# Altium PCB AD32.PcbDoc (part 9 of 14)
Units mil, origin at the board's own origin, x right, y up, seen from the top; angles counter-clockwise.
Board outline 7007.87 x 4368.85 mil, 12 copper layers (Top Layer, Int1 (GND), Int2 (AVDD), Int3 (DVDD), Int4 (GND), Int5 (ST), Int6 (SB), Int8 (AGND), Int7 (AVCC), Int9 (VCCA), Int10 (GND), Bottom Layer), stack 60.136 mil thick; 1350 components, 880 nets, 4712 pads, 2835 vias.
Unrouted connection lines stored in the file: 19.
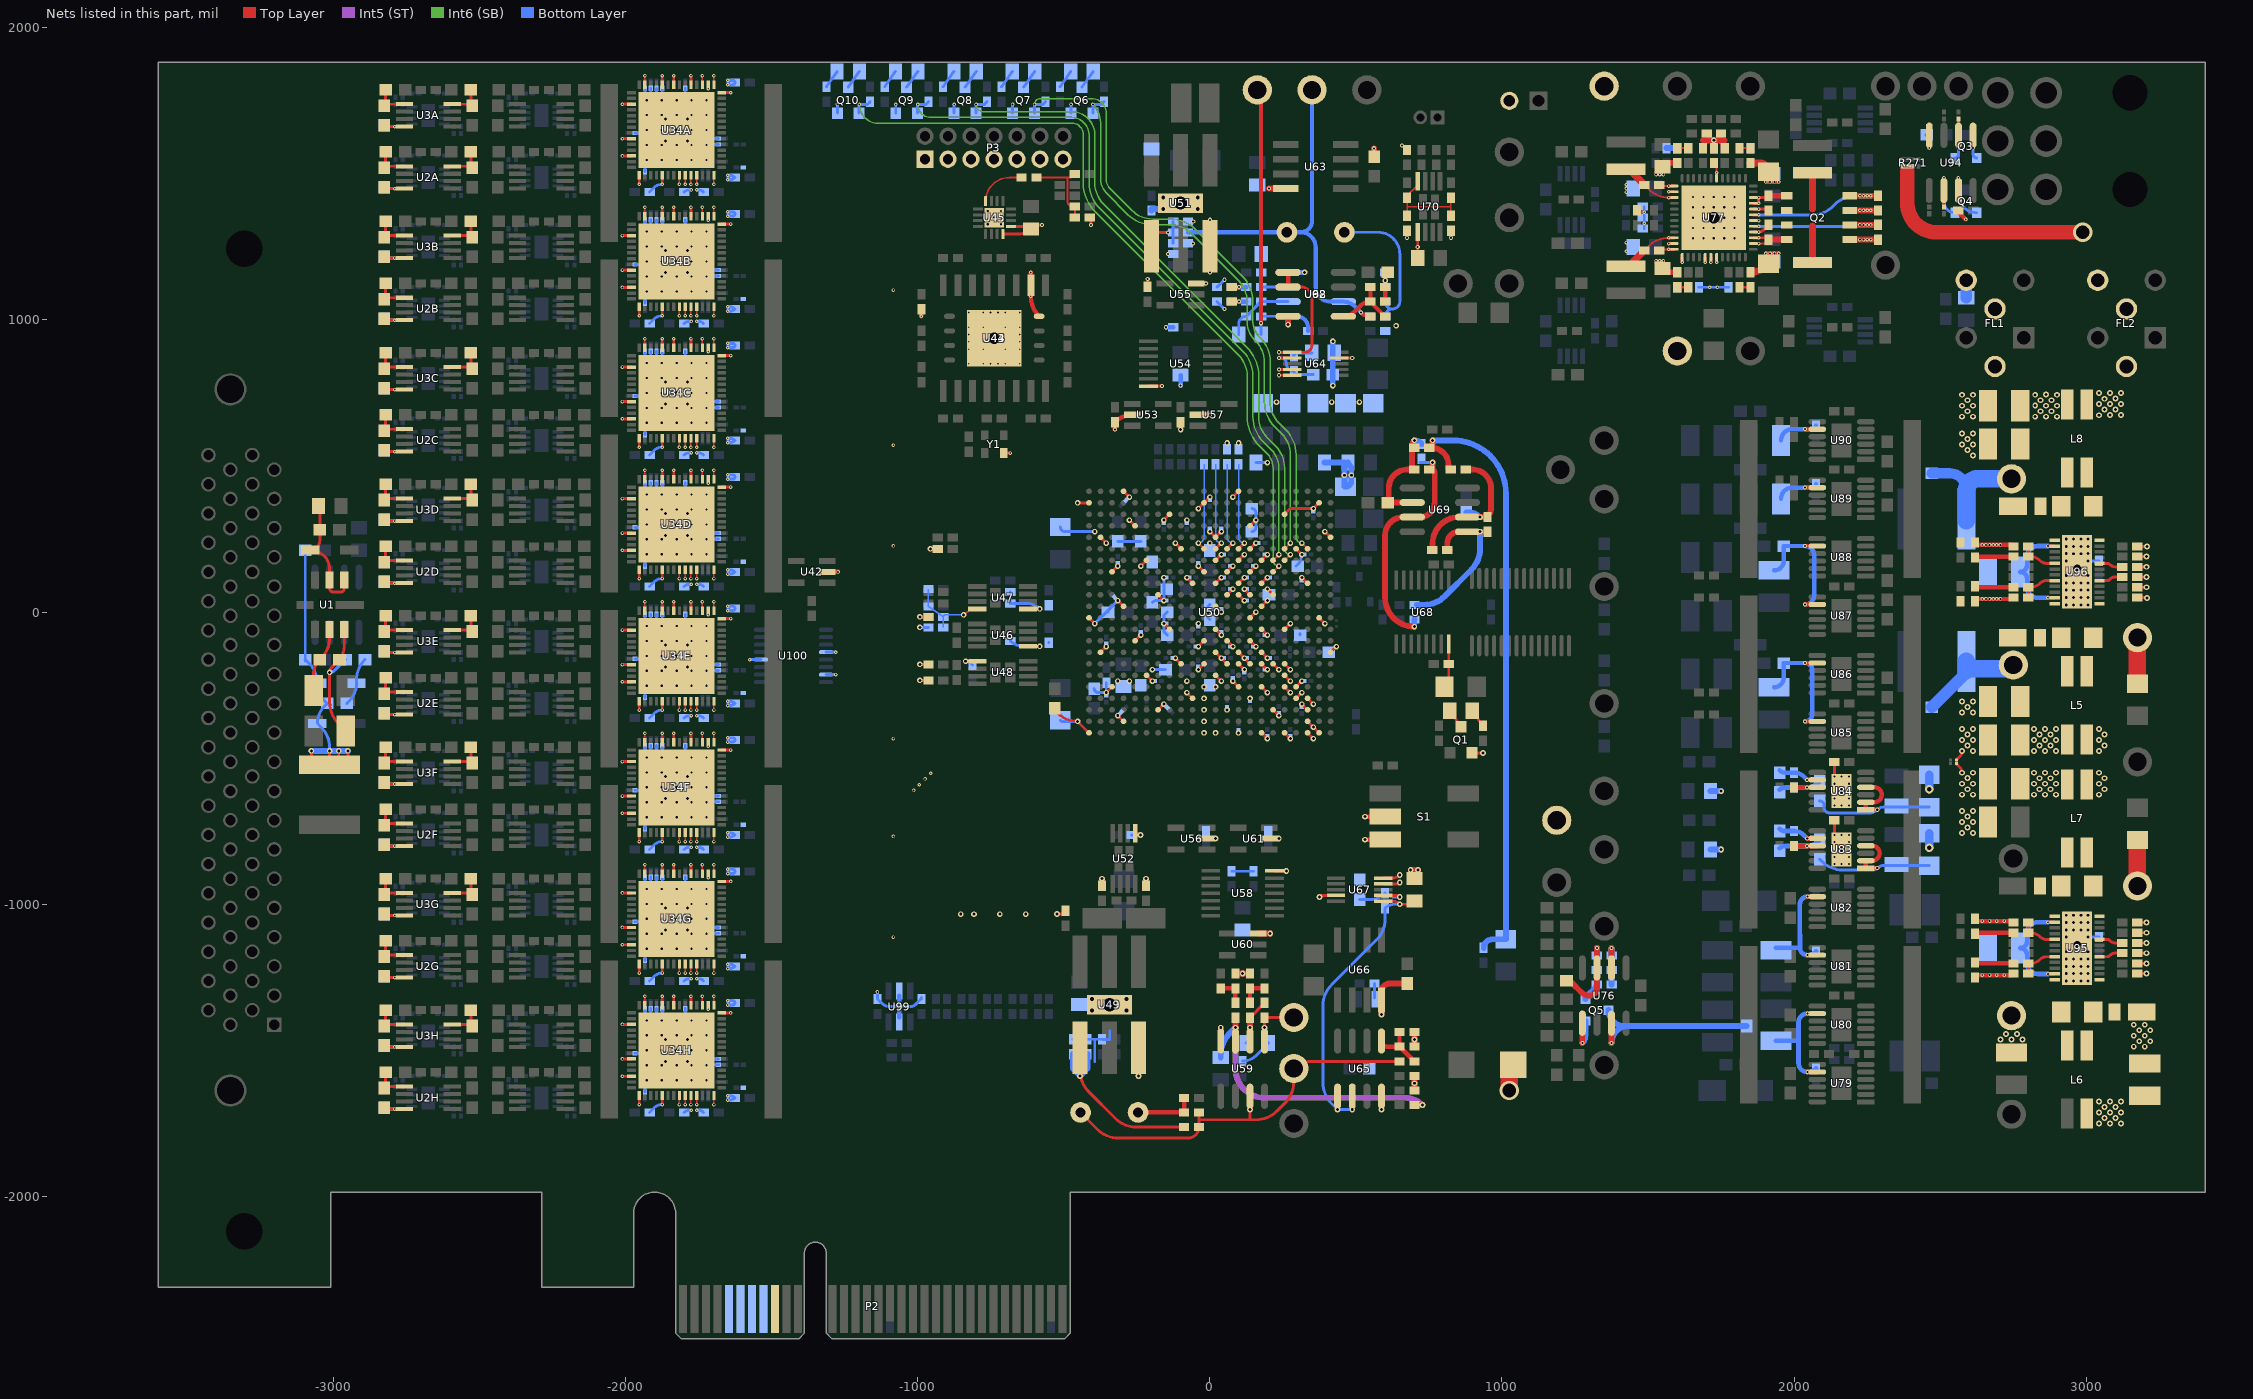
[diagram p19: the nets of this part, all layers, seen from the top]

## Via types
v1: diameter 12, hole 6, Top Layer to Bottom Layer, tented both sides, 1497 vias
v2: diameter 20, hole 10, Top Layer to Bottom Layer, tented both sides, 364 vias
v3: diameter 19, hole 10, Top Layer to Bottom Layer, tented both sides, 347 vias
v4: diameter 14, hole 7, Top Layer to Bottom Layer, tented both sides, 228 vias
v5: diameter 19.68, hole 7.87, Top Layer to Bottom Layer, 225 vias
v6: diameter 19.02, hole 10, Top Layer to Bottom Layer, tented both sides, 85 vias
v7: diameter 20, hole 10, Top Layer to Bottom Layer, 32 vias
v8: diameter 40, hole 20, Top Layer to Bottom Layer, tented both sides, 14 vias
v9: diameter 30, hole 15, Top Layer to Bottom Layer, tented both sides, 12 vias
v10: diameter 25, hole 13, Top Layer to Bottom Layer, 8 vias
v11: diameter 40, hole 20, Top Layer to Bottom Layer, 6 vias
v12: diameter 50, hole 20, Top Layer to Bottom Layer, 6 vias
v13: diameter 66, hole 47, Top Layer to Bottom Layer, tented both sides, 3 vias
v14: diameter 63, hole 45, Top Layer to Bottom Layer, 2 vias
v15: diameter 50, hole 25, Top Layer to Bottom Layer, 2 vias
v16: diameter 12, hole 6, Top Layer to Bottom Layer, 2 vias
v17: diameter 60, hole 40, Top Layer to Bottom Layer, tented both sides, 1 vias
v18: diameter 60, hole 40, Top Layer to Bottom Layer, 1 vias

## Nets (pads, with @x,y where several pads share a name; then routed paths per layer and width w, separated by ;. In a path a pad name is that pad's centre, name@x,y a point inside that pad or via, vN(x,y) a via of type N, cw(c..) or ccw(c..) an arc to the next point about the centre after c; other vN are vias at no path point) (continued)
GND: (continued)
  other v2: 700.59,-1612.5 3162.5,-1487.5 3200,-1487.5 3181.25,-1468.75 3218.75,-1468.75 700.59,-1462.5 2706.25,-1462.5 2743.75,-1462.5 2781.25,-1462.5 3162.5,-1450 3200,-1450 2725,-1443.75 2762.5,-1443.75 3181.25,-1431.25 3218.75,-1431.25 3162.5,-1412.5 3200,-1412.5 2931.25,-1262.5 2956.25,-1262.5 2981.25,-1262.5 3006.25,-1262.5 2931.25,-1237.5 2956.49,-1237.69 2981.49,-1237.69 3006.25,-1237.5 112.5,-1236.91 2931.25,-1212.5 2956.49,-1212.69 2981.25,-1212.5 3006.25,-1212.5 2931.25,-1187.5 2956.25,-1187.5 2981.25,-1187.5 3006.25,-1187.5 2931.25,-1162.5 3006.25,-1162.5 2931.25,-1112.5 2931.25,-1087.5 2956.49,-1087.69 2981.49,-1087.69 3006.25,-1087.5 2931.25,-1062.5 2956.49,-1062.69 2981.49,-1062.69 3006.25,-1062.5 2931.25,-1037.5 2956.25,-1037.5 2981.25,-1037.5 3006.25,-1037.5 2575,-756.25 2612.5,-756.25 2593.75,-737.5 2575,-718.75 2612.5,-718.75 2593.75,-700 2575,-681.25 2612.5,-681.25 2575,-625 2612.5,-625 3043.75,-625 2593.75,-606.25 3062.5,-606.25 2575,-587.5 2612.5,-587.5 3043.75,-587.5 3062.5,-568.75 2593.75,-567.5 2575,-550 2612.5,-550 3043.75,-550 2612.5,-475 3043.75,-475 2593.75,-456.25 3062.5,-456.25 2575,-437.5 2612.5,-437.5 3043.75,-437.5 2593.75,-418.75 3062.5,-418.75 2575,-400 2612.5,-400 3043.75,-400 2575,-343.75 2612.5,-343.75 2593.75,-325 2575,-306.25 2612.5,-306.25 2931.25,25 2956.25,25 2981.25,25 3006.25,25 2956.49,49.81 2981.49,49.81 2931.25,50 3006.25,50 2956.49,74.81 2931.25,75 2981.25,75 3006.25,75 2931.25,100 2956.25,100 2981.25,100 3006.25,100 2931.25,125 3006.25,125 2931.25,175 2956.49,199.81 2981.49,199.81 2931.25,200 3006.25,200 2956.49,224.81 2981.49,224.81 2931.25,225 3006.25,225 2931.25,250 2956.25,250 2981.25,250 3006.25,250 2612.5,536.25 2593.75,555 2575,573.75 2612.5,573.75 2593.75,592.5 2575,611.25 2612.5,611.25 2575,668.75 2612.5,668.75 3043.75,673.75 3081.25,675 3118.75,675 2593.75,687.5 3062.5,693.75 3100,693.75 2575,706.25 2612.5,706.25 3043.75,712.5 3081.25,712.5 3118.75,712.5 2593.75,725 3062.5,730 3100,731.25 2575,743.75 2612.5,743.75 3043.75,750 3081.25,750 3118.75,750
  other v3: -19.68,-413.39 19.69,-413.39 98.43,-413.39 -19.68,-374.02 -19.68,-334.65 59.06,-334.65 -19.68,-295.28 137.8,-295.28 -19.68,-255.91 19.69,-255.91 -314.96,-236.22 -275.59,-236.22 -78.74,-236.22 -39.37,-39.37 -6.25,-1.25 0,236.22 -78.74,314.96 59.06,578.74 98.43,578.74 228.35,718.5 417.32,718.5 511.81,718.5
  other v4: 2137.5,-862.5 2162.5,-862.5 2187.5,-862.5 2137.5,-837.5 2187.5,-837.5 2137.5,-787.5 2187.5,-787.5 2162.5,-762.5 2187.5,-762.5 2137.5,-662.5 2162.5,-662.5 2187.5,-662.5 2137.5,-637.5 2187.5,-637.5 2137.5,-587.5 2187.5,-587.5 2162.5,-562.5 2187.5,-562.5 0,1162.74 -143.31,1225 711.61,1250 -57.72,1261.53 -56.69,1337.5 0,1342.74
  other v5: -1876.18,-1551.18 -1825,-1551.18 -1773.82,-1551.18 -1876.18,-1500 -1825,-1500 -1773.82,-1500 -1876.18,-1448.82 -1825,-1448.82 -1773.82,-1448.82 -1876.18,-1101.18 -1825,-1101.18 -1773.82,-1101.18 -1876.18,-1050 -1825,-1050 -1773.82,-1050 -1876.18,-998.82 -1825,-998.82 -1773.82,-998.82 -1876.18,-651.18 -1825,-651.18 -1773.82,-651.18 -1876.18,-600 -1825,-600 -1773.82,-600 -1876.18,-548.82 -1825,-548.82 -1773.82,-548.82 -1876.18,-201.18 -1825,-201.18 -1773.82,-201.18 -1876.18,-150 -1825,-150 -1773.82,-150 -1876.18,-98.82 -1825,-98.82 -1773.82,-98.82 -1876.18,248.82 -1825,248.82 -1773.82,248.82 -1876.18,300 -1825,300 -1773.82,300 -1876.18,351.18 -1825,351.18 -1773.82,351.18 -1876.18,698.82 -1825,698.82 -1773.82,698.82 -1876.18,750 -1825,750 -1773.82,750 -1876.18,801.18 -1825,801.18 -1773.82,801.18 -1876.18,1148.82 -1825,1148.82 -1773.82,1148.82 -1876.18,1200 -1825,1200 -1773.82,1200 -1876.18,1251.18 -1825,1251.18 -1773.82,1251.18 1654.13,1279.13 1689.57,1279.13 1725,1279.13 1760.43,1279.13 1795.87,1279.13 1654.13,1314.57 1689.57,1314.57 1725,1314.57 1760.43,1314.57 1795.87,1314.57 1654.13,1350 1689.57,1350 1725,1350 1760.43,1350 1795.87,1350 1654.13,1385.43 1689.57,1385.43 1725,1385.43 1760.43,1385.43 1795.87,1385.43 1654.13,1420.87 1689.57,1420.87 1725,1420.87 1760.43,1420.87 1795.87,1420.87 -1876.18,1598.82 -1825,1598.82 -1773.82,1598.82 -1876.18,1650 -1825,1650 -1773.82,1650 -1876.18,1701.18 -1825,1701.18 -1773.82,1701.18
  other v6: -852.36,-1033.46 -807.09,-1033.46 -718.5,-1033.46 -629.92,-1033.46 637.5,980 600.59,1134.56
  other v10: -402.81,-1363.43 -284.69,-1363.43 -402.81,-1324.06 -284.69,-1324.06 -40.94,1380.06 -159.06,1419.43 -40.94,1419.43
  other v11: 2162.5,-812.5 2162.5,-612.5
  other v14: -343.75,-1343.75 -100,1399.74
  other v15: 2968.75,-1137.5 2968.75,150
  other v17: -737.5,937.5
  other v18: 1725,1350
INIT: R369.1 U50.U12 | length 308.8
  Top Layer w5: v3(-39.37,236.22) U50.U12@-19.68,216.54
  Bottom Layer w5: v3(-39.37,236.22) ccw(c-39.37,255.91) -19.68,255.91 R369.1@-19.69,505.91
JTAG1: P2.B9
JTAG2: P2.A5
JTAG3: P2.A6
JTAG4: P2.A7
JTAG5: P2.A8
LED_A: Q10.1 R399.1 U50.R6 | length 2662.1
  Top Layer w5: U50.R6@216.54,137.8 v3(236.22,157.48)
  Int6 (SB) w5: v1(-1200,1737.5) ccw(c-1135.73,1737.5) -1135.73,1673.23 -472.44,1673.23 cw(c-472.44,1633.86) -433.07,1633.86 -433.07,1468.6 ccw(c-293.7,1468.6) -392.25,1370.05 98.66,879.13 cw(c27.95,808.42) 127.95,808.42 127.95,667.97 ccw(c267.32,667.97) 168.77,569.42 196.85,541.34 cw(c149.33,493.82) 216.54,493.82 216.54,177.17 ccw(c236.22,177.17) v3(236.22,157.48)
  Bottom Layer w10: Q10.1@-1200.1,1708.21 -1200,1725.39 v1(-1200,1737.5) -1171.91,1737.5 R399.1@-1162.5,1746.91
LED_B: Q9.1 R394.1 U50.T6 | length 2431.2
  Top Layer w5: U50.T6@216.54,177.17 v3(236.22,196.85)
  Int6 (SB) w5: v1(-1000,1737.5) ccw(c-955.41,1737.5) -955.41,1692.91 -472.44,1692.91 cw(c-472.44,1633.86) -413.39,1633.86 -413.39,1468.6 ccw(c-293.7,1468.6) -378.33,1383.97 112.58,893.05 cw(c27.95,808.42) 147.64,808.42 147.64,667.97 ccw(c267.32,667.97) 182.69,583.34 210.77,555.26 cw(c149.33,493.82) 236.22,493.82 v3(236.22,196.85)
  Bottom Layer w10: Q9.1@-1000.1,1708.21 -1000,1708.31 v1(-1000,1737.5) -971.91,1737.5 R394.1@-962.5,1746.91
LED_C: Q8.1 R389.1 U50.T5 | length 2262.2
  Top Layer w5: U50.T5@255.91,177.17 v3(275.59,196.85)
  Int6 (SB) w5: v1(-800,1737.5) ccw(c-775.1,1737.5) -775.1,1712.6 -472.44,1712.6 cw(c-472.44,1633.86) -393.7,1633.86 -393.7,1468.6 ccw(c-293.7,1468.6) -364.41,1397.88 126.5,906.97 cw(c27.95,808.42) 167.32,808.42 167.32,667.97 ccw(c267.32,667.97) 196.61,597.25 224.69,569.18 cw(c149.33,493.82) 255.91,493.82 255.91,216.54 ccw(c275.59,216.54) v3(275.59,196.85)
  Bottom Layer w10: Q8.1@-800.1,1708.21 -800,1708.31 v1(-800,1737.5) -771.91,1737.5 R389.1@-762.5,1746.91
LED_D: Q7.1 R381.1 U50.U3 | length 2190.7
  Top Layer w5: v3(314.96,236.22) U50.U3@334.65,216.54
  Int6 (SB) w5: v1(-600,1737.5) cw(c-579.63,1737.5) -579.63,1757.87 -405.51,1757.87 cw(c-405.51,1706.69) -354.33,1706.69 -354.33,1482.09 ccw(c-307.28,1482.09) -340.55,1448.82 -266.32,1374.59 ccw(c-195.61,1445.3) -195.61,1345.3 -134.75,1345.3 cw(c-134.75,1225.61) -50.12,1310.24 112.58,1147.54 cw(c27.95,1062.91) 147.64,1062.91 147.64,992.41 ccw(c214.85,992.41) 167.32,944.88 171.64,940.57 cw(c87.01,855.94) 206.69,855.94 206.69,718.87 ccw(c306.69,718.87) 235.98,648.16 260.22,623.92 cw(c175.59,539.29) 295.28,539.29 295.28,255.91 ccw(c314.96,255.91) v3(314.96,236.22)
  Bottom Layer w10: Q7.1@-600.1,1708.21 -600,1708.31 v1(-600,1737.5) -571.91,1737.5 R381.1@-562.5,1746.91
LED_PG: Q6.1 R378.1 U50.U5 | length 1930.7
  Top Layer w5: U50.U5@255.91,216.54 v3(275.59,236.22)
  Int6 (SB) w5: v1(-400,1737.5) cw(c-462.73,1674.77) -374.02,1674.77 -374.02,1482.09 ccw(c-307.28,1482.09) -354.47,1434.9 -280.24,1360.67 ccw(c-195.61,1445.3) -195.61,1325.61 -134.75,1325.61 cw(c-134.75,1225.61) -64.04,1296.32 98.66,1133.62 cw(c27.95,1062.91) 127.95,1062.91 127.95,992.41 ccw(c214.85,992.41) 153.4,930.96 157.72,926.65 cw(c87.01,855.94) 187.01,855.94 187.01,718.87 ccw(c306.69,718.87) 222.06,634.24 246.3,610 cw(c175.59,539.29) 275.59,539.29 v3(275.59,236.22)
  Bottom Layer w10: Q6.1@-400.1,1708.21 -400,1708.31 v1(-400,1737.5) -371.91,1737.5 R378.1@-362.5,1746.91
M0: R367.1 U50.U11 | length 308.8
  Top Layer w10: U50.U11@19.69,216.54 v3(39.37,236.22)
  Bottom Layer w5: R367.1@19.69,505.91 19.69,255.91 ccw(c39.37,255.91) v3(39.37,236.22)
M1: R366.1 U50.U10 | length 308.8
  Top Layer w10: U50.U10@59.06,216.54 v3(78.74,236.22)
  Bottom Layer w5: R366.1@59.06,505.91 59.06,255.91 ccw(c78.74,255.91) v3(78.74,236.22)
M2: R365.1 U50.U9 | length 308.8
  Top Layer w10: U50.U9@98.43,216.54 v3(118.11,236.22)
  Bottom Layer w5: R365.1@98.43,505.91 98.43,255.91 ccw(c118.11,255.91) v3(118.11,236.22)
MON: C52.2 R181.2 R182.1 U65.5 | length 194.8
  Top Layer w15: U65.5@587.5,-1468.01 ccw(c606.99,-1468.01) 606.99,-1487.5 R182.1@649.41,-1487.5 ; C52.2@649.41,-1437.5 R182.1@649.41,-1487.5 ; R182.1@650.42,-1487.92 ccw(c649.41,-1488.93) R182.1@649.41,-1487.5 ; R182.1@650.42,-1487.92 699.58,-1537.08 ccw(c700.59,-1536.07) R181.2@700.59,-1537.5
MON2: C48.2 R178.2 R179.1 U62.5 | length 230.7
  Top Layer w14: 517.5,1050 cw(c547.68,1019.82) 547.68,1062.5 R179.1@549.41,1062.5 ; C48.2@549.41,1112.5 R179.1@549.41,1062.5 ; R179.1@550.59,1062.01 600.1,1012.5 R178.2@600.59,1012.5 ; R179.1@550.58,1062.02 ccw(c549.41,1060.84) R179.1@549.41,1062.5
  Top Layer w15: U62.5@456.99,1012.5 ccw(c456.99,1068.06) 496.27,1028.77 517.5,1050
NetC1_2: C1.2 D1.2 D2.1 R1.1 R665.2 R666.2 | length 1188
  Top Layer w10: v3(-3075,-475) -3075,-522.64 C1.2@-3012.5,-522.64 ; v3(-3012.5,-475) C1.2@-3012.5,-522.64 ; v3(-2981.25,-475) C1.2@-2981.25,-522.64 ; v3(-2950,-475) -2950,-522.64 C1.2@-2981.25,-522.64 ; C1.2@-3012.5,-522.64 C1.2@-2981.25,-522.64
  Bottom Layer w10: R665.2@-3096.25,-162.5 R665.2@-3095.96,-162.21 ; R665.2@-3095.96,-167.04 R665.2@-3095.96,-162.5 ; R666.2@-3095.96,212.5 R665.2@-3095.96,-162.21 ; D1.2@-3060.43,-237.75 D1.2@-3054.43,-243.75 ; v3(-3012.5,-475) -3012.5,-464.6 ccw(c-3112.5,-464.6) -3041.79,-393.89 D2.1@-3054.43,-381.25 cw(c-2969.24,-381.25) -3029.48,-321.01 R1.1@-3020.96,-312.5 -3029.48,-303.99 cw(c-2969.24,-243.75) D1.2@-3054.43,-243.75 ; R665.2@-3095.96,-162.5 -3082.51,-175.95 cw(c-3150.31,-243.75) D1.2@-3054.43,-243.75 ; R665.2@-3095.96,-162.5 R665.2@-3095.96,-162.21
  Bottom Layer w20: v3(-3075,-475) v3(-3012.5,-475) v3(-2981.25,-475) v3(-2950,-475)
NetC2_2: C2.2 D3.2 R2.1 U1.1 U1.2 | length 434
  Top Layer w10: C2.2@-3050.89,362.5 cw(c-3050.89,357.58) -3045.96,357.58 R2.1@-3045.96,281.25 -3045.96,245.96 cw(c-3079.43,245.96) D3.2@-3079.43,212.5 cw(c-3079.43,145.57) -3012.5,145.57 U1.2@-3012.5,109.65 -3012.5,81.25 ccw(c-3000,81.25) -3000,68.75 -2975,68.75 ccw(c-2975,81.25) -2962.5,81.25 U1.1@-2962.5,109.65
NetC5_1: C5.1 R5.1 R6.1 R7.2 | length 293.5
  Top Layer w6: R6.1@-593.16,1487.5 -487.5,1487.5 ; C5.1@-461.84,1350 R5.1@-461.84,1387.5 -468.5,1387.5 cw(c-468.5,1406.5) -487.5,1406.5 -487.5,1487.5 ; R7.2@-461.84,1500 cw(c-474.34,1500) -474.34,1487.5 -487.5,1487.5
NetC7_1: C7.1 R3.2 R8.2 U1.7 | length 458.7
  Top Layer w10: R8.2@-2979.04,-162.5 R8.2@-2983.21,-166.68 ; U1.7@-2962.5,-59.65 -2962.5,-116.68 cw(c-3033.21,-116.68) R8.2@-2983.21,-166.68 ; C7.1@-2957.38,-406.25 -2983.21,-380.42 cw(c-2912.5,-309.71) -3012.5,-309.71 v3(-3012.5,-206.25) cw(c-2987.67,-206.25) -3005.23,-188.69 R8.2@-2983.21,-166.68
  Bottom Layer w10: v3(-3012.5,-206.25) ccw(c-3012.5,-181.42) -2994.94,-198.98 R3.2@-2958.46,-162.5
NetC8_1: C8.1 R8.1 U1.6 | length 224.5
  Top Layer w10: C8.1@-3067.62,-268.75 -3067.62,-214.78 cw(c-2993.69,-214.78) R8.1@-3045.96,-162.5 -3041.79,-158.32 ccw(c-3112.5,-87.61) -3012.5,-87.61 U1.6@-3012.5,-59.65
NetC38_1: C38.1 C43.2 R168.2 | length 207.6
  Top Layer w15: C38.1@-245.65,-1712.5 C43.2@-88.09,-1712.5 R168.2@-88.09,-1662.5
NetC38_2: C38.2 C43.1 R169.2 R181.1 TP5.1 U59.7 | length 1397.6
  Top Layer w10: C38.2@-442.5,-1712.5 -384.29,-1770.71 ccw(c-313.58,-1700) -313.58,-1800 -74.41,-1800 ccw(c-74.41,-1762.5) R169.2@-36.91,-1762.5 -36.91,-1737.5 ; C43.1@-36.91,-1712.5 -36.91,-1737.5 ; U59.7@137.5,-1656.99 v2(137.5,-1702.5) 137.5,-1737.5 ; R181.1@649.41,-1537.5 347.86,-1537.5 ccw(c347.86,-1622.86) TP5.1@287.5,-1562.5 287.5,-1608.58 cw(c187.5,-1608.58) 258.21,-1679.29 229.29,-1708.21 cw(c158.58,-1637.5) 158.58,-1737.5 137.5,-1737.5 ; -36.91,-1737.5 137.5,-1737.5
NetC44_2: C44.2 R172.2 R173.1 | length 98.8
  Top Layer w15: R172.2@37.5,-1288.09 C44.2@87.5,-1288.09 R173.1@87.5,-1336.91
NetC45_1: C45.1 R174.1 R176.2 | length 98.8
  Top Layer w15: R174.1@137.5,-1336.91 C45.1@137.5,-1288.09 R176.2@187.5,-1288.09
NetC46_1: C46.1 C147.2 R355.2 | length 512.6
  Bottom Layer w10: C46.1@460.63,1300 575.49,1300 cw(c575.49,1225) 650.49,1225 650.49,1062.99 cw(c625,1062.99) 625,1037.5 ; C147.2@600.59,1012.5 600.59,1013.09 cw(c625,1013.09) 625,1037.5 ; R355.2@600.59,1062.5 600.59,1061.91 ccw(c625,1061.91) 625,1037.5
NetC46_2: C46.2 C147.1 R178.1 R373.2 TP7.1 U98.7 | length 1379.5
  Top Layer w14: v4(517.5,1025) ccw(c547.68,1055.18) 547.68,1012.5 R178.1@549.41,1012.5
  Bottom Layer w14: R373.2@-74.41,1299.75 -74.41,1300 C46.2@263.78,1300 310.72,1300 ; TP7.1@350,1787.5 350,1339.28 cw(c310.72,1339.28) 310.72,1300 ; C147.1@549.41,1012.5 547.68,1012.5 cw(c547.68,1055.18) v4(517.5,1025) 496.27,1046.23 ccw(c456.99,1006.94) U98.7@456.99,1062.5 412.5,1062.5 cw(c412.5,1112.5) 362.5,1112.5 362.5,1248.22 ccw(c310.72,1248.22) 310.72,1300
NetC54_1: C54.1 R356.2 U65.1 U65.2 U67.1 | length 1092.5
  Top Layer w10: v2(437.5,-1702.5) U65.1@437.5,-1656.99 ; v2(487.5,-1702.5) U65.2@487.5,-1656.99 ; U67.1@593.21,-989.37 624.34,-989.37 cw(c624.34,-1025.66) v2(650,-1000) 671.96,-1000 ccw(c671.96,-960.35) C54.1@700,-988.39
  Bottom Layer w10: v2(487.5,-1702.5) v2(437.5,-1702.5) 416.79,-1681.79 cw(c487.5,-1611.08) 387.5,-1611.08 387.5,-1346.42 cw(c487.5,-1346.42) 416.79,-1275.71 570.71,-1121.79 ccw(c500,-1051.08) 600,-1051.08 R356.2@600,-1013.09 cw(c631.6,-1044.69) 631.6,-1000 v2(650,-1000)
NetC58_2: C58.2 FR2.1 U68.16 | length 150.6
  Top Layer w10: FR2.1@803.15,-255.91 ccw(c767.51,-220.26) 817.91,-220.26 C58.2@817.91,-177.17 U68.16@817.91,-109.25
NetC61_2: C61.2 R183.1 R184.1 R193.2 U70.4 | length 341.2
  Top Layer w5: R183.1@675,1356.84 675,1387.5 ; U70.4@711.25,1473.75 cw(c681.07,1473.75) 702.41,1452.41 679.84,1429.84 ccw(c691.51,1418.16) R184.1@675,1418.16 675,1387.5 ; C61.2@825,1356.84 825,1387.5 ; R193.2@825,1418.16 825,1387.5 ; 675,1387.5 825,1387.5
NetC62_1: C62.1 R189.2 R354.1 U69.1 | length 557.8
  Top Layer w20: R189.2@820.96,212.5 cw(c820.96,220.96) 812.5,220.96 812.5,234.83 cw(c852.67,234.83) 852.67,275 U69.1@881.99,275 948.57,275 cw(c948.57,272.98) C62.1@950,274.41
  Bottom Layer w20: R354.1@708.46,25 733.58,25 ccw(c733.58,125) 804.29,54.29 895.71,145.71 ccw(c825,216.42) 925,216.42 v3@925,275
  other v3: 925,275.59
NetC62_2: C62.2 R189.1 R192.2 R352.2 U69.2 | length 535.7
  Top Layer w20: R189.1@754.04,212.5 ccw(c754.04,220.96) 762.5,220.96 762.5,234.83 cw(c852.67,234.83) 852.67,325 U69.2@881.99,325 v3(925,325) 948.57,325 ccw(c948.57,327.02) C62.2@950,325.59 ccw(c919.82,355.77) 962.5,355.77 962.5,425 ccw(c900,425) 900,487.5 R192.2@883.46,487.5
  Bottom Layer w20: R352.2@877.5,341.54 885.08,341.54 cw(c885.08,285.08) v3(925,325)
NetC65_1: C65.1 L1.1 U77.10 | length 200.2
  Top Layer w7: C65.1@1486.91,1237.5 1501.88,1252.47 cw(c1571,1183.36) v1(1571,1281.1)
  Top Layer w10: v1(1571,1281.1) U77.10@1590.16,1281.1
  Top Layer w25: L1.1@1425,1184.15 ccw(c1425,1204.83) 1439.62,1190.21 C65.1@1486.91,1237.5
NetC65_2: C65.2 U77.12 | length 53.2
  Top Layer w7: C65.2@1538.09,1237.5 cw(c1548.31,1227.28) 1548.31,1241.73 v1(1571,1241.73)
  Top Layer w10: v1(1571,1241.73) U77.12@1590.16,1241.73
NetC66_1: C66.1 L2.1 U77.3 | length 200.2
  Top Layer w7: C66.1@1486.91,1462.5 1501.88,1447.53 ccw(c1571,1516.64) v1(1571,1418.9)
  Top Layer w10: v1(1571,1418.9) U77.3@1590.16,1418.9
  Top Layer w25: L2.1@1425,1515.85 cw(c1425,1495.17) 1439.62,1509.79 C66.1@1486.91,1462.5
NetC66_2: C66.2 U77.1 | length 53.2
  Top Layer w7: C66.2@1538.09,1462.5 ccw(c1548.31,1472.72) 1548.31,1458.27 v1(1571,1458.27)
  Top Layer w10: v1(1571,1458.27) U77.1@1590.16,1458.27
NetC70_2: C70.2 R216.1 | length 37.5
  Top Layer w10: C70.2@1600,1111.91 R216.1@1637.5,1111.91
NetC71_2: C71.2 R217.1 | length 37.5
  Top Layer w7: C71.2@1600,1588.09 R217.1@1637.5,1588.09
NetC73_2: C73.2 U77.42 | length 54.7
  Top Layer w7: C73.2@1725,1536.91 cw(c1701.24,1513.15) 1734.84,1513.15 v1(1734.84,1504.04)
  Top Layer w10: U77.42@1734.84,1484.84 v1(1734.84,1504.04)
NetC74_2: C74.2 R229.1 | length 37.5
  Top Layer w7: R229.1@1812.5,1111.91 C74.2@1850,1111.91
NetC75_2: C75.2 R230.1 | length 37.5
  Top Layer w7: R230.1@1812.5,1588.09 C75.2@1850,1588.09
NetC78_1: C78.1 U77.28 | length 62
  Top Layer w10: U77.28@1859.84,1300.79 v1(1878.54,1300.79) ccw(c1878.54,1322.9) 1894.17,1307.27 C78.1@1912.5,1325.59
NetC78_2: C78.2 L3.1 Q2.7 Q2.8 U77.26 U77.27 | length 303.4
  Top Layer w8: v1(1878.54,1261.42) 1899.51,1261.42 ccw(c1899.51,1274.41) C78.2@1912.5,1274.41 ; v1(1878.54,1281.1) 1905.81,1281.1 cw(c1905.81,1274.41) C78.2@1912.5,1274.41 ; C78.2@1913.93,1275 ccw(c1913.93,1272.98) C78.2@1912.5,1274.41
  Top Layer w10: U77.26@1859.84,1261.42 v1(1878.54,1261.42) ; U77.27@1859.84,1281.1 v1(1878.54,1281.1)
  Top Layer w20: C78.2@1913.93,1275 Q2.8@1975,1275
  Top Layer w25: L3.1@2062.5,1196.65 2062.5,1320.81
NetC79_1: C79.1 U77.32 | length 54
  Top Layer w10: U77.32@1859.84,1379.53 v1(1878.54,1379.53) 1900.14,1379.53 cw(c1900.14,1362.05) C79.1@1912.5,1374.41
NetC79_2: C79.2 L4.1 Q2.5 Q2.6 U77.33 U77.34 | length 278.9
  Top Layer w10: U77.33@1859.84,1399.21 v1(1878.54,1399.21) v1(1878.54,1418.9) ; U77.34@1859.84,1418.9 v1(1878.54,1418.9) ; C79.2@1912.5,1425.59 cw(c1896.34,1441.75) 1896.34,1418.9 v1(1878.54,1418.9)
  Top Layer w20: C79.2@1912.5,1425.59 ccw(c1913.93,1427.02) 1913.93,1425 Q2.5@1975,1425
  Top Layer w25: 2062.5,1379.96 L4.1@2062.5,1503.35
NetC80_2: C80.2 R312.2 U89.8 | length 190.8
  Top Layer w15: v4(2037.5,426.25) 2079.07,426.25 U89.8@2079.44,425.89
  Bottom Layer w15: C80.2@1955.12,387.5 cw(c1993.87,387.5) 1993.87,426.25 v4(2037.5,426.25) 2063.16,426.25 ccw(c2063.16,438.09) R312.2@2075,438.09
NetC81_2: C81.2 R313.2 U90.8 | length 190.8
  Top Layer w15: v4(2037.5,626.25) 2079.07,626.25 U90.8@2079.44,625.89
  Bottom Layer w15: C81.2@1955.12,587.5 cw(c1993.87,587.5) 1993.87,626.25 v4(2037.5,626.25) 2063.16,626.25 ccw(c2063.16,638.09) R313.2@2075,638.09
NetC82_1: C82.1 R277.2 | length 133.7
  Top Layer w15: C82.1@2618.75,-1199.41 ccw(c2621.84,-1199.41) 2621.84,-1202.5 R277.2@2750.66,-1202.5
NetC83_2: C83.2 R281.1 | length 133.7
  Top Layer w15: C83.2@2618.75,-1100.59 cw(c2621.84,-1100.59) 2621.84,-1097.5 R281.1@2750.66,-1097.5
NetC84_1: C84.1 R278.2 | length 133.7
  Top Layer w15: C84.1@2618.75,88.09 ccw(c2621.84,88.09) 2621.84,85 R278.2@2750.66,85
NetC85_2: C85.2 R284.1 | length 133.7
  Top Layer w15: C85.2@2618.75,186.91 cw(c2621.84,186.91) 2621.84,190 R284.1@2750.66,190
NetC87_1: C87.1 C105.2 C106.1 FR5.2 L6.4 L7.4 R287.2 R289.2 TP38.1 U95.2 U95.11 | length 583.9
  Top Layer w10: v1(2868.75,-1238.58) U95.11@2892.25,-1238.58 ; v1(2868.75,-1061.42) U95.2@2892.25,-1061.42 ; R287.2@3174.34,-1237.5 v2(3206.25,-1237.5) ; R289.2@3174.34,-1062.5 v2(3206.25,-1062.5)
  Top Layer w60: TP38.1@3175,-937.5 FR5.2@3175,-780.12
  Bottom Layer w16: v1(2868.75,-1238.58) 2833.58,-1238.58 cw(c2833.58,-1202.5) 2797.5,-1202.5 2797.5,-1173.63 ccw(c2773.87,-1173.63) C106.1@2773.87,-1150 ccw(c2773.87,-1126.37) 2797.5,-1126.37 2797.5,-1097.5 cw(c2833.58,-1097.5) 2833.58,-1061.42 v1(2868.75,-1061.42)
  other v2: 3043.75,-1750 3081.25,-1750 3118.75,-1750 3062.5,-1731.25 3100,-1731.25 3043.75,-1712.5 3081.25,-1712.5 3118.75,-1712.5 3062.5,-1693.75 3100,-1693.75 3043.75,-1675 3081.25,-1675 3118.75,-1675 2821.25,-625 2858.75,-625 2896.25,-625 2840,-606.25 2877.5,-606.25 2821.25,-587.5 2858.75,-587.5 2896.25,-587.5 2840,-568.75 2877.5,-568.75 2821.25,-550 2858.75,-550 2896.25,-550
NetC88_2: C88.2 C91.1 C107.1 FR6.2 L5.3 L8.4 R290.2 R292.2 TP40.1 U96.2 U96.11 | length 586.7
  Top Layer w10: v1(2868.75,48.92) U96.11@2892.25,48.92 ; v1(2868.75,226.08) U96.2@2892.25,226.08 ; R290.2@3174.34,50 3204.48,50 cw(c3204.48,45.73) v2(3207.5,48.75) ; R292.2@3174.34,225 v2(3207.5,225)
  Top Layer w60: FR6.2@3175,-244.88 TP40.1@3175,-87.5
  Bottom Layer w16: v1(2868.75,48.92) 2833.58,48.92 cw(c2833.58,85) 2797.5,85 2797.5,113.87 ccw(c2773.87,113.87) C107.1@2773.87,137.5 ccw(c2773.87,161.13) 2797.5,161.13 2797.5,190 cw(c2833.58,190) 2833.58,226.08 v1(2868.75,226.08)
  other v2: 2821.25,-475 2858.75,-475 2896.25,-475 2840,-456.25 2877.5,-456.25 2821.25,-437.5 2858.75,-437.5 2896.25,-437.5 2840,-418.75 2877.5,-418.75 2821.25,-400 2858.75,-400 2896.25,-400 2825,668.75 2862.5,668.75 2900,668.75 2843.75,687.5 2881.25,687.5 2862.5,706.25 2900,706.25 2825,707.5 2843.75,725 2881.25,725 2825,743.75 2900,743.75 2862.13,744.61
NetC89_2: C89.2 C108.2 D6.2 R275.1 R301.2 TP37.1 | length 352.5
  Bottom Layer w40: R301.2@2470.96,-325 2585.55,-210.42 ccw(c2575.13,-200) C108.2@2589.86,-200
  Bottom Layer w60: C108.2@2589.86,-200 C108.2@2589.86,-193.75 ; C108.2@2589.86,-168.75 C108.2@2589.86,-193.75 ; TP37.1@2737.5,-193.75 C108.2@2589.86,-193.75
NetC90_1: C90.1 C109.1 D7.2 R276.2 R302.2 TP35.1 | length 426.6
  Bottom Layer w35: R302.2@2470.96,475 2531.69,475 cw(c2531.69,416.83) C109.1@2589.86,416.83
  Bottom Layer w60: C109.1@2589.86,312.5 2589.86,416.83 cw(c2629.28,416.83) 2629.28,456.25 TP35.1@2737.5,456.25
NetC93_1: C93.1 R277.1 U95.8 | length 131.6
  Top Layer w10: C93.1@2801.84,-1237.5 R277.1@2801.84,-1202.5 2807.54,-1202.5 ccw(c2807.54,-1151.29) 2843.75,-1187.5 cw(c2863,-1206.75) 2863,-1179.53 U95.8@2892.25,-1179.53
NetC94_1: C94.1 R278.1 U96.8 | length 131.6
  Top Layer w10: C94.1@2801.84,50 R278.1@2801.84,85 2807.54,85 ccw(c2807.54,136.21) 2843.75,100 cw(c2863,80.75) 2863,107.97 U96.8@2892.25,107.97
NetC95_2: C95.2 R281.2 U95.5 | length 131.6
  Top Layer w10: C95.2@2801.84,-1062.5 R281.2@2801.84,-1097.5 2807.54,-1097.5 cw(c2807.54,-1148.71) 2843.75,-1112.5 ccw(c2863,-1093.25) 2863,-1120.47 U95.5@2892.25,-1120.47
NetC96_2: C96.2 R284.2 U96.5 | length 131.6
  Top Layer w10: C96.2@2801.84,225 R284.2@2801.84,190 2807.54,190 cw(c2807.54,138.79) 2843.75,175 ccw(c2863,194.25) 2863,167.03 U96.5@2892.25,167.03
NetC97_1: C97.1 D5.1 L7.1
NetC97_2: C97.2 L7.2 U95.1 U95.24
NetC98_1: C98.1 D8.1 L6.1
NetC98_2: C98.2 L6.2 U95.12 U95.13
NetC99_1: C99.1 D6.1 L5.2
NetC99_2: C99.2 L5.1 U96.12 U96.13
NetC100_1: C100.1 D7.1 L8.1
NetC100_2: C100.2 L8.2 U96.1 U96.24
NetC101_2: C101.2 U95.20 | length 81.1
  Top Layer w10: U95.20@3045.25,-1120.47 3070.32,-1120.47 cw(c3070.32,-1135.93) 3081.25,-1125 ccw(c3099.36,-1106.89) 3099.36,-1132.5 C101.2@3123.16,-1132.5
NetC102_2: C102.2 U96.20 | length 81.1
  Top Layer w10: U96.20@3045.25,167.03 3070.32,167.03 cw(c3070.32,151.57) 3081.25,162.5 ccw(c3099.36,180.61) 3099.36,155 C102.2@3123.16,155
NetC103_1: C103.1 U95.17 | length 81.5
  Top Layer w10: U95.17@3045.25,-1179.53 3070.32,-1179.53 ccw(c3070.32,-1164.07) 3081.25,-1175 3083.47,-1172.78 cw(c3096.21,-1185.51) 3096.21,-1167.5 C103.1@3123.16,-1167.5
NetC104_1: C104.1 U96.17 | length 81.5
  Top Layer w10: U96.17@3045.25,107.97 3070.32,107.97 ccw(c3070.32,123.43) 3081.25,112.5 3083.47,114.72 cw(c3096.21,101.99) 3096.21,120 C104.1@3123.16,120
NetC114_2: C114.2 C119.2 L9.2 U83.1 U83.2 U83.4 | length 577.3
  Top Layer w15: U83.4@2245.56,-799.7 2267.2,-799.7 cw(c2267.2,-825) 2292.5,-825 cw(c2266.61,-825) 2266.61,-850.89 U83.2@2245.56,-850.89 U83.1@2245.56,-876.48 v4(2284.43,-876.48)
  Bottom Layer w10: C119.2@2087.5,-845.96 2094.75,-853.21 ccw(c2165.46,-782.5) 2165.46,-882.5 2269.88,-882.5 ccw(c2269.88,-861.93) v4(2284.43,-876.48) cw(c2305.81,-897.86) 2305.81,-867.62 C114.2@2462.5,-867.62
NetC115_2: C115.2 C118.2 L10.2 U84.1 U84.2 U84.4 | length 609.8
  Top Layer w15: U84.4@2245.56,-599.7 2274.7,-599.7 cw(c2274.7,-625) 2300,-625 cw(c2274.11,-625) 2274.11,-650.89 U84.2@2245.56,-650.89 U84.1@2245.56,-676.48 v4(2284.43,-676.48)
  Bottom Layer w10: C118.2@2087.5,-645.96 cw(c2087.5,-660.07) 2101.61,-660.07 2101.61,-667.62 ccw(c2121.49,-667.62) 2121.49,-687.5 2257.81,-687.5 ccw(c2257.81,-649.86) v4(2284.43,-676.48) cw(c2305.81,-697.86) 2305.81,-667.62 C115.2@2462.5,-667.62
NetC120_1: C120.1 R309.1 U79.8 U80.8 | length 413.5
  Top Layer w16: v4(2045.19,-1574.11) U79.8@2079.44,-1574.11 ; v4(2045.19,-1374.11) U80.8@2079.44,-1374.11
  Bottom Layer w16: C120.1@1937.5,-1467.62 2015,-1467.62 ; v4(2045.19,-1374.11) ccw(c2045.19,-1404.31) 2015,-1404.31 2015,-1467.62 ; R309.1@2075,-1561.91 cw(c2045.54,-1532.44) 2045.54,-1574.11 v4(2045.19,-1574.11) cw(c2045.19,-1543.92) 2015,-1543.92 2015,-1467.62
NetC121_2: C121.2 R310.2 U81.8 U82.8 | length 420.5
  Top Layer w16: v4(2045.19,-1174.11) U81.8@2079.44,-1174.11 ; v4(2045.19,-974.11) U82.8@2079.44,-974.11
  Bottom Layer w16: C121.2@1937.5,-1148.92 2020,-1148.92 ; 2019.6,-1112.5 2019.6,-999.7 cw(c2045.19,-999.7) v4(2045.19,-974.11) ; 2020,-1105 2020,-1148.92 ; R310.2@2075,-1161.91 cw(c2045.54,-1132.44) 2045.54,-1174.11 v4(2045.19,-1174.11) cw(c2045.19,-1148.92) 2020,-1148.92
NetC122_2: C122.2 R231.1 U85.8 U86.8 | length 487.2
  Top Layer w15: v4(2037.5,-374.11) U85.8@2079.44,-374.11 ; v4(2037.5,-174.11) U86.8@2079.44,-174.11
  Bottom Layer w15: C122.2@1931.25,-257.38 ccw(c1931.25,-223.92) 1964.71,-223.92 R231.1@1964.71,-175 cw(c1965.6,-175) 1965.6,-174.11 v4(2037.5,-174.11) cw(c2037.5,-199.11) 2062.5,-199.11 2062.5,-349.11 cw(c2037.5,-349.11) v4(2037.5,-374.11)
NetC123_2: C123.2 R232.2 U87.8 U88.8 | length 494.4
  Top Layer w15: v4(2037.5,26.25) 2079.07,26.25 U87.8@2079.44,25.89 ; v4(2037.5,226.25) 2079.07,226.25 U88.8@2079.44,225.89
  Bottom Layer w15: C123.2@1931.25,142.62 ccw(c1931.25,176.08) 1964.71,176.08 R232.2@1964.71,225 cw(c1965.96,225) 1965.96,226.25 v4(2037.5,226.25) cw(c2037.5,195.37) 2068.38,195.37 2068.38,57.13 cw(c2037.5,57.13) v4(2037.5,26.25)
NetC124_2: C124.2 R314.2 U83.8 | length 140.7
  Top Layer w16: v4(2044.83,-774.79) 2079.44,-774.79 U83.8@2079.44,-774.11
  Bottom Layer w16: C124.2@1950,-741.54 ccw(c1969.01,-722.53) 1969.01,-749.41 R314.2@2000,-749.41 cw(c2000,-796.37) 2033.21,-763.16 v4(2044.83,-774.79)
NetC125_2: C125.2 R315.2 U84.8 | length 139.7
  Top Layer w15: v4(2044.47,-574.11) U84.8@2079.44,-574.11
  Bottom Layer w15: C125.2@1950,-541.54 ccw(c1969.01,-522.53) 1969.01,-549.41 R315.2@2000,-549.41 cw(c2000,-597.14) 2033.75,-563.39 v4(2044.47,-574.11)
NetC141_1: C141.1 R200.1 R347.2 U76.7 | length 348.7
  Top Layer w20: R200.1@1220.96,-1262.5 cw(c1220.96,-1290.35) 1240.66,-1270.66 1270.13,-1300.13 ccw(c1300,-1270.25) 1300,-1312.5 ccw(c1300,-1287.5) 1325,-1287.5 U76.7@1325,-1218.01 v4(1325,-1150)
  Bottom Layer w20: C141.1@1324.41,-1225 ccw(c1322.98,-1223.57) 1325,-1223.57 v4(1325,-1150)
NetC141_2: C141.2 R346.2 R347.1 U76.6 | length 193.2
  Top Layer w20: U76.6@1375,-1218.01 v4(1375,-1150)
  Bottom Layer w20: v4(1375,-1150) 1375,-1175 1375,-1225 1375,-1273.57 ccw(c1377.02,-1273.57) R346.2@1375.59,-1275
NetC145_2: C145.2 FR7.2 R186.1 R192.1 | length 2110.9
  Top Layer w20: R186.1@762.5,562.5 R186.1@758.46,562.5 ; v3(762.5,587.5) 762.5,572.24 cw(c748.72,572.24) R186.1@758.46,562.5 ; R192.1@816.54,487.5 816.54,504.43 ccw(c758.46,504.43) R186.1@758.46,562.5
  Bottom Layer w20: v3(762.5,587.5) 832.53,587.5 cw(c832.53,406.74) 1013.29,406.74 1013.29,-1117.97 cw(c1010.59,-1117.97) FR7.2@1012.5,-1119.88 967.03,-1119.88 ccw(c967.03,-1149.41) C145.2@937.5,-1149.41
NetC146_1: C146.1 R187.2 R353.1 U69.7 | length 817
  Top Layer w20: v3(700,-50) cw(c700,50) 600,50 600,263.58 cw(c661.42,263.58) 661.42,325 U69.7@693.01,325 718.71,325 ccw(c718.71,376.29) 770,376.29 770,475.96 ccw(c758.46,475.96) 758.46,487.5 ccw(c748.72,497.24) 762.5,497.24 v3(762.5,512.5)
  Bottom Layer w10: C146.1@720,512.5 v3(762.5,512.5)
  Bottom Layer w20: v3(700,-50) 700,-25 R353.1@700.59,-25
NetC146_2: C146.2 R177.2 R186.2 R187.1 U69.6 | length 381.2
  Top Layer w20: U69.6@693.01,375 R177.2@608.46,375 ccw(c598.72,384.74) 612.5,384.74 612.5,425 cw(c675,425) 675,487.5 691.54,487.5 691.54,562.5 691.54,567.06 cw(c720.44,567.06) v3(700,587.5)
  Bottom Layer w20: v3(700,587.5) cw(c700,555.9) 722.35,578.24 C146.2@725,575.59
NetC159_2: C159.2 R356.1 U67.2 | length 205
  Top Layer w10: U67.2@593.21,-969.68 637.17,-969.68 cw(c637.17,-987.83) v2(650,-975)
  Bottom Layer w10: C159.2@512.5,-983.46 547.96,-983.46 ccw(c547.96,-909.87) R356.1@600,-961.91 ccw(c631.6,-930.31) 631.6,-975 v2(650,-975)
NetC161_2: C161.2 R359.1 U64.2 | length 193.7
  Top Layer w10: v4(237.5,869.69) U64.2@281.79,869.69
  Bottom Layer w10: v4(237.5,869.69) 242.82,869.69 cw(c242.82,850) 262.5,850 262.5,849.41 ccw(c287.5,849.41) R359.1@287.5,824.41 ccw(c299.41,824.41) 299.41,812.5 C161.2@354.04,812.5
NetC162_1: C162.1 R359.2 U62.1 U62.2 U64.1 | length 567
  Top Layer w10: v4(237.5,889.37) U64.1@281.79,889.37 324.8,889.37 ccw(c324.8,914.57) 350,914.57 350,1075 ccw(c312.5,1075) 312.5,1112.5 U62.2@268.01,1112.5
  Top Layer w15: U62.2@268.01,1112.5 U62.1@268.01,1162.5
  Bottom Layer w10: v4(237.5,889.37) 273.72,889.37 cw(c273.72,875.59) R359.2@287.5,875.59 cw(c299.41,875.59) 299.41,887.5 C162.1@349.11,887.5
NetC181_1: C181.1 R175.2 R364.1 TP6.1 U59.1 | length 352.4
  Top Layer w10: U59.1@187.5,-1468.01 v2(187.5,-1422.5) R175.2@187.5,-1388.09 cw(c188.93,-1389.52) 188.93,-1387.5 TP6.1@287.5,-1387.5
  Bottom Layer w10: R364.1@112.5,-1536.91 ccw(c112.5,-1472.99) 157.7,-1518.19 C181.1@200.89,-1475 ; v2@188.58,-1422.5 v2(187.5,-1422.5) 187.5,-1452.76 ccw(c208.89,-1452.76) 193.76,-1467.88 C181.1@200.89,-1475 ; C181.1@198.37,-1476.04 cw(c200.89,-1478.56) C181.1@200.89,-1475
NetC181_2: C181.2 R174.2 R175.1 U59.2 | length 208.8
  Top Layer w10: R174.2@137.5,-1388.09 186.66,-1338.93 ccw(c184.65,-1336.91) R175.1@187.5,-1336.91
  Top Layer w20: U59.2@137.5,-1468.01 v2(137.5,-1422.5) R174.2@137.5,-1388.09
  Bottom Layer w10: C181.2@124.11,-1475 131.24,-1467.88 ccw(c116.11,-1452.76) 137.5,-1452.76 v2(137.5,-1422.5)
NetC186_1: C186.1 R358.1 R360.2 TP3.1 U98.1 | length 1062.9
  Top Layer w14: TP3.1@162.5,1787.5 cw(c162.5,1774.11) 175.89,1774.11 v4(175.89,988.78)
  Bottom Layer w10: R360.2@175.59,1012.5 R360.2@175.89,1012.5 ; C186.1@175.89,950 R360.2@175.89,1012.5 ; U98.1@268.01,1012.5 R360.2@175.89,1012.5
  Bottom Layer w14: U98.1@268.01,1012.5 297.16,1012.5 cw(c297.16,973.22) 336.44,973.22 R358.1@336.44,962.5
NetC186_2: C186.2 R360.1 R361.2 U98.2 | length 241.1
  Bottom Layer w10: C186.2@99.11,950 99.11,987.2 cw(c124.41,987.2) R360.1@124.41,1012.5 ccw(c124.41,1013.93) R360.1@125.42,1012.92 ; R360.1@125.42,1012.92 174.58,1062.08 cw(c175.59,1061.07) R361.2@175.59,1062.5 U98.2@268.01,1062.5
NetC192_2: C192.2 R362.2 R363.1 U98.3 | length 205.5
  Bottom Layer w10: 175.89,1197.44 175.59,1197.15 ; C192.2@175.89,1225 175.59,1224.7 175.59,1197.15 ; U98.3@268.01,1112.5 R362.2@175.59,1112.5 175.59,1197.15
NetC208_2: C208.2 R171.2 R362.1 | length 73.2
  Top Layer w15: R171.2@75.59,1112.5 v4(100,1112.5)
  Bottom Layer w15: C208.2@75.59,1112.5 v4(100,1112.5) R362.1@124.41,1112.5
NetC209_1: C209.1 R170.2 R361.1 | length 73.2
  Top Layer w15: R170.2@75.59,1062.5 v4(100,1062.5)
  Bottom Layer w15: C209.1@75.59,1062.5 v4(100,1062.5) R361.1@124.41,1062.5
NetC221_2: C221.2 R173.2 R180.1 U59.3 | length 1068.8
  Top Layer w20: U59.3@87.5,-1468.01 v2(87.5,-1422.5) R173.2@87.5,-1388.09 ; R180.1@700.59,-1687.5 v2(727.61,-1687.5)
  Int5 (ST) w20: v2(87.5,-1422.5) 87.5,-1562.5 ccw(c187.5,-1562.5) 187.5,-1662.5 667.25,-1662.5 cw(c667.25,-1747.86) v2(727.61,-1687.5)
  Bottom Layer w20: C221.2@37.5,-1524.11 37.5,-1513.92 cw(c137.5,-1513.92) 66.79,-1443.21 v2(87.5,-1422.5)
NetC248_1: C248.1 R373.1 R376.1 U51.1 | length 178.7
  Top Layer w10: U51.1@-200,1252.74 -200,1299.75 v4(-143.31,1299.75)
  Bottom Layer w10: R376.1@-125.59,1262.5 R373.1@-125.59,1299.75 C248.1@-125.59,1337.5
NetC264_1: C264.1 R169.1 R377.1 U49.1 | length 716.9
  Top Layer w10: U49.1@-443.75,-1490.75 -443.75,-1571.08 ccw(c-343.75,-1571.08) -414.46,-1641.79 -323.04,-1733.21 ccw(c-252.33,-1662.5) -252.33,-1762.5 R169.1@-88.09,-1762.5
  Top Layer w20: v2(-443.75,-1587.5) U49.1@-443.75,-1571.08
  Bottom Layer w20: C264.1@-468.75,-1513.09 -468.75,-1562.5 v2(-443.75,-1587.5) -418.75,-1562.5 R377.1@-418.75,-1513.09
NetC285_2: C285.2 R390.1 R391.2 R392.1 U47.4 | length 283.4
  Top Layer w5: v3(-842.52,-9.84) -840.5,-7.83 cw(c-795.47,-52.86) U47.4@-795.47,10.83
  Bottom Layer w5: R391.2@-963.07,78.74 R390.1@-963.07,19.69 C285.2@-911.89,-16.3 ; R392.1@-911.91,-52.1 C285.2@-911.89,-16.3 ; v3(-842.52,-9.84) -905.43,-9.84 ccw(c-905.43,-16.3) C285.2@-911.89,-16.3
NetD1_1: D1.1 R1.2 R3.1 | length 171.6
  Bottom Layer w10: R1.2@-2954.04,-312.5 -2945.52,-303.99 ccw(c-3005.76,-243.75) D1.1@-2920.57,-243.75 ; D1.1@-2918.94,-243.75 D1.1@-2920.57,-243.75 ; R3.1@-2893.5,-162.5 R3.1@-2891.54,-162.5 ccw(c-2821.44,-232.6) -2920.57,-232.6 D1.1@-2920.57,-243.75
NetD4_2: D4.2 R271.4 | length 857.7
  Top Layer w50: 2387.5,1507.5 2387.5,1400 ccw(c2487.5,1400) 2487.5,1300 v13(2987.5,1300)
  Top Layer w60: v13(1025,-1637.5) 1025,-1563.58 D4.2@1038.58,-1550
NetDS1_1: DS1.1 Q1.3 | length 67.7
  Top Layer w10: DS1.1@821.61,-337.5 Q1.3@860,-393.21
NetDS1_2: DS1.2 R195.2 | length 63.5
  Top Layer w10: DS1.2@898.39,-337.5 R195.2@935,-389.41
NetDS2_1: DS2.1 Q6.3 | length 65.6
  Bottom Layer w10: Q6.3@-437.5,1796.79 DS2.1@-399.11,1850
NetDS2_2: DS2.2 R380.2 | length 63.5
  Bottom Layer w10: R380.2@-512.5,1798.09 DS2.2@-475.89,1850
NetDS3_1: DS3.1 Q7.3 | length 65.6
  Bottom Layer w10: Q7.3@-637.5,1796.79 DS3.1@-599.11,1850
NetDS3_2: DS3.2 R388.2 | length 63.5
  Bottom Layer w10: R388.2@-712.5,1798.09 DS3.2@-675.89,1850
NetDS4_1: DS4.1 Q8.3 | length 65.6
  Bottom Layer w10: Q8.3@-837.5,1796.79 DS4.1@-799.11,1850
NetDS4_2: DS4.2 R393.2 | length 63.5
  Bottom Layer w10: R393.2@-912.5,1798.09 DS4.2@-875.89,1850
NetDS5_1: DS5.1 Q9.3 | length 65.6
  Bottom Layer w10: Q9.3@-1037.5,1796.79 DS5.1@-999.11,1850
NetDS5_2: DS5.2 R398.2 | length 63.5
  Bottom Layer w10: R398.2@-1112.5,1798.09 DS5.2@-1075.89,1850
NetDS6_1: DS6.1 Q10.3 | length 65.6
  Bottom Layer w10: Q10.3@-1237.5,1796.79 DS6.1@-1199.11,1850
NetDS6_2: DS6.2 R400.2 | length 63.5
  Bottom Layer w10: R400.2@-1312.5,1798.09 DS6.2@-1275.89,1850
NetQ2_2: Q2.2 R258.1 U77.29 | length 513.9
  Top Layer w10: U77.29@1859.84,1320.47 v1(1878.54,1320.47)
  Top Layer w20: Q2.2@2190.16,1325 v1(2225,1325) v1(2237.5,1325) v1(2250,1325) v1(2262.5,1325) 2286.07,1325 ccw(c2286.07,1327.02) R258.1@2287.5,1325.59
  Bottom Layer w10: v1(1878.54,1320.47) 2226.57,1320.47 ccw(c2226.57,1335.93) v1(2237.5,1325)
  Bottom Layer w20: v1(2225,1325) v1(2237.5,1325) v1(2250,1325) v1(2262.5,1325)
NetQ2_4: Q2.4 R259.1 U77.31 | length 518.5
  Top Layer w10: U77.31@1859.84,1359.84 v1(1878.54,1359.84)
  Top Layer w20: Q2.4@2190.16,1425 v1(2225,1425) v1(2237.5,1425) v1(2250,1425) v1(2262.5,1425) 2286.07,1425 ccw(c2286.07,1427.02) R259.1@2287.5,1425.59
  Bottom Layer w10: v1(1878.54,1359.84) 2062.61,1359.84 ccw(c2062.61,1459.84) 2133.32,1389.13 2139.9,1395.71 cw(c2210.61,1325) 2210.61,1425 v1(2225,1425)
  Bottom Layer w20: v1(2225,1425) v1(2237.5,1425) v1(2250,1425) v1(2262.5,1425)
NetQ3_1: Q3.1 U94.1 | length 84.7
  Top Layer w10: v1(2612.5,1588.68) U94.1@2612.5,1631.99
  Bottom Layer w10: v1(2612.5,1588.68) 2612.5,1566.78 ccw(c2624.9,1566.78) Q3.1@2624.9,1554.38
NetQ3_2: Q3.2 R272.1 U94.2 | length 140.8
  Top Layer w10: v1(2562.5,1588.68) U94.2@2562.5,1631.99 R272.1@2562.5,1688.06
  Bottom Layer w10: Q3.2@2550.1,1554.38 ccw(c2550.1,1566.78) 2562.5,1566.78 v1(2562.5,1588.68)
NetQ4_1: Q4.1 U94.7 | length 198.4
  Top Layer w10: U94.7@2562.5,1443.01 v1(2562.5,1486.32)
  Bottom Layer w10: v1(2562.5,1486.32) 2562.5,1429.28 ccw(c2624.9,1429.28) Q4.1@2624.9,1366.88
NetQ4_2: Q4.2 R297.2 U94.6 | length 240.3
  Top Layer w10: R297.2@2512.5,1386.94 U94.6@2512.5,1443.01 v1(2512.5,1486.32)
  Bottom Layer w10: v1(2512.5,1486.32) 2512.5,1404.48 ccw(c2550.1,1404.48) Q4.2@2550.1,1366.88
NetQ5_1: Q5.1 U76.1 | length 146
  Top Layer w20: v4(1275,-1475) U76.1@1275,-1406.99
  Bottom Layer w20: v4(1275,-1475) ccw(c1249.34,-1449.34) 1285.63,-1449.34 Q5.1@1285.63,-1399.9
NetQ5_2: Q5.2 R346.1 | length 65
  Bottom Layer w20: Q5.2@1285.63,-1325.1 cw(c1299.46,-1325.1) 1289.67,-1315.33 1320.46,-1284.54 ccw(c1310.91,-1275) R346.1@1324.41,-1275
NetQ5_3: Q5.3 R325.2 U76.3 | length 663.8
  Top Layer w20: v4(1375,-1475) U76.3@1375,-1406.99
  Bottom Layer w20: Q5.3@1364.37,-1362.5 ccw(c1418.41,-1362.5) 1418.41,-1416.54 1433.46,-1416.54 ; v4(1375,-1475) cw(c1433.46,-1475) 1433.46,-1416.54 ; R325.2@1837.5,-1416.54 1433.46,-1416.54
NetR4A_1: R4A.1 R657A.2 U3A.8 | length 107.4
  Top Layer w10: R4A.1@-2825,1666.41 ccw(c-2820.08,1666.41) -2820.08,1661.49 -2790,1661.49 U3A.8@-2756.69,1661.49
  Bottom Layer w10: R657A.2@-2825,1666.54 ccw(c-2813.12,1678.42) -2813.12,1661.61 v1(-2790,1661.61)
NetR4A_2: R4A.2 R20A.1 U3A.5 | length 126.4
  Top Layer w10: R4A.2@-2820.96,1738.39 R4A.2@-2820.96,1738.31 ; R20A.1@-2820.96,1787.37 R4A.2@-2820.96,1738.31 ; R4A.2@-2820.08,1738.26 U3A.5@-2756.69,1738.26 ; R4A.2@-2820.08,1738.39 R4A.2@-2825,1733.46 cw(c-2820.08,1733.46) R4A.2@-2820.96,1738.31
NetR4B_1: R4B.1 R657B.2 U3B.8 | length 107.4
  Top Layer w10: R4B.1@-2825,1216.41 ccw(c-2820.08,1216.41) -2820.08,1211.49 -2790,1211.49 U3B.8@-2756.69,1211.49
  Bottom Layer w10: R657B.2@-2825,1216.54 ccw(c-2813.12,1228.42) -2813.12,1211.61 v1(-2790,1211.61)
NetR4B_2: R4B.2 R20B.1 U3B.5 | length 126.4
  Top Layer w10: R4B.2@-2820.96,1288.39 R4B.2@-2820.96,1288.31 ; R20B.1@-2820.96,1337.37 R4B.2@-2820.96,1288.31 ; R4B.2@-2820.08,1288.26 U3B.5@-2756.69,1288.26 ; R4B.2@-2820.08,1288.39 R4B.2@-2825,1283.46 cw(c-2820.08,1283.46) R4B.2@-2820.96,1288.31
NetR4C_1: R4C.1 R657C.2 U3C.8 | length 107.4
  Top Layer w10: R4C.1@-2825,766.41 ccw(c-2820.08,766.41) -2820.08,761.49 -2790,761.49 U3C.8@-2756.69,761.49
  Bottom Layer w10: R657C.2@-2825,766.54 ccw(c-2813.12,778.42) -2813.12,761.61 v1(-2790,761.61)
NetR4C_2: R4C.2 R20C.1 U3C.5 | length 126.4
  Top Layer w10: R4C.2@-2820.96,838.39 R4C.2@-2820.96,838.31 ; R20C.1@-2820.96,887.37 R4C.2@-2820.96,838.31 ; R4C.2@-2820.08,838.26 U3C.5@-2756.69,838.26 ; R4C.2@-2820.08,838.39 R4C.2@-2825,833.46 cw(c-2820.08,833.46) R4C.2@-2820.96,838.31
NetR4D_1: R4D.1 R657D.2 U3D.8 | length 107.4
  Top Layer w10: R4D.1@-2825,316.41 ccw(c-2820.08,316.41) -2820.08,311.49 -2790,311.49 U3D.8@-2756.69,311.49
  Bottom Layer w10: R657D.2@-2825,316.54 ccw(c-2813.12,328.42) -2813.12,311.61 v1(-2790,311.61)
NetR4D_2: R4D.2 R20D.1 U3D.5 | length 126.4
  Top Layer w10: R4D.2@-2820.96,388.39 R4D.2@-2820.96,388.31 ; R20D.1@-2820.96,437.37 R4D.2@-2820.96,388.31 ; R4D.2@-2820.08,388.26 U3D.5@-2756.69,388.26 ; R4D.2@-2820.08,388.39 R4D.2@-2825,383.46 cw(c-2820.08,383.46) R4D.2@-2820.96,388.31
NetR4E_1: R4E.1 R657E.2 U3E.8 | length 107.4
  Top Layer w10: R4E.1@-2825,-133.59 ccw(c-2820.08,-133.59) -2820.08,-138.51 -2790,-138.51 U3E.8@-2756.69,-138.51
  Bottom Layer w10: R657E.2@-2825,-133.46 ccw(c-2813.12,-121.58) -2813.12,-138.39 v1(-2790,-138.39)
NetR4E_2: R4E.2 R20E.1 U3E.5 | length 126.4
  Top Layer w10: R4E.2@-2820.96,-61.61 R4E.2@-2820.96,-61.69 ; R20E.1@-2820.96,-12.63 R4E.2@-2820.96,-61.69 ; R4E.2@-2820.08,-61.74 U3E.5@-2756.69,-61.74 ; R4E.2@-2820.08,-61.61 R4E.2@-2825,-66.54 cw(c-2820.08,-66.54) R4E.2@-2820.96,-61.69
NetR4F_1: R4F.1 R657F.2 U3F.8 | length 107.4
  Top Layer w10: R4F.1@-2825,-583.59 ccw(c-2820.08,-583.59) -2820.08,-588.51 -2790,-588.51 U3F.8@-2756.69,-588.51
  Bottom Layer w10: R657F.2@-2825,-583.46 ccw(c-2813.12,-571.58) -2813.12,-588.39 v1(-2790,-588.39)
NetR4F_2: R4F.2 R20F.1 U3F.5 | length 126.4
  Top Layer w10: R4F.2@-2820.96,-511.61 R4F.2@-2820.96,-511.69 ; R20F.1@-2820.96,-462.63 R4F.2@-2820.96,-511.69 ; R4F.2@-2820.08,-511.74 U3F.5@-2756.69,-511.74 ; R4F.2@-2820.08,-511.61 R4F.2@-2825,-516.54 cw(c-2820.08,-516.54) R4F.2@-2820.96,-511.69
NetR4G_1: R4G.1 R657G.2 U3G.8 | length 107.4
  Top Layer w10: R4G.1@-2825,-1033.59 ccw(c-2820.08,-1033.59) -2820.08,-1038.51 -2790,-1038.51 U3G.8@-2756.69,-1038.51
  Bottom Layer w10: R657G.2@-2825,-1033.46 ccw(c-2813.12,-1021.58) -2813.12,-1038.39 v1(-2790,-1038.39)
NetR4G_2: R4G.2 R20G.1 U3G.5 | length 126.4
  Top Layer w10: R4G.2@-2820.96,-961.61 R4G.2@-2820.96,-961.69 ; R20G.1@-2820.96,-912.63 R4G.2@-2820.96,-961.69 ; R4G.2@-2820.08,-961.74 U3G.5@-2756.69,-961.74 ; R4G.2@-2820.08,-961.61 R4G.2@-2825,-966.54 cw(c-2820.08,-966.54) R4G.2@-2820.96,-961.69
NetR4H_1: R4H.1 R657H.2 U3H.8 | length 107.4
  Top Layer w10: R4H.1@-2825,-1483.59 ccw(c-2820.08,-1483.59) -2820.08,-1488.51 -2790,-1488.51 U3H.8@-2756.69,-1488.51
  Bottom Layer w10: R657H.2@-2825,-1483.46 ccw(c-2813.12,-1471.58) -2813.12,-1488.39 v1(-2790,-1488.39)
NetR4H_2: R4H.2 R20H.1 U3H.5 | length 126.4
  Top Layer w10: R4H.2@-2820.96,-1411.61 R4H.2@-2820.96,-1411.69 ; R20H.1@-2820.96,-1362.63 R4H.2@-2820.96,-1411.69 ; R4H.2@-2820.08,-1411.74 U3H.5@-2756.69,-1411.74 ; R4H.2@-2820.08,-1411.61 R4H.2@-2825,-1416.54 cw(c-2820.08,-1416.54) R4H.2@-2820.96,-1411.69
NetR6_2: R6.2 U45.8 | length 168.9
  Top Layer w6: U45.8@-767.03,1406.5 cw(c-686.02,1406.5) -686.02,1487.5 R6.2@-644.34,1487.5
NetR12A_1: R12A.1 R649A.2 U2A.8 | length 105.9
  Top Layer w10: R12A.1@-2825,1454.04 ccw(c-2813.12,1465.92) -2813.12,1449.11 v1(-2790,1449.11) U2A.8@-2756.69,1449.11
  Bottom Layer w10: R649A.2@-2825,1454.04 ccw(c-2813.12,1465.92) -2813.12,1449.11 v1(-2790,1449.11)
NetR12A_2: R12A.2 R28A.1 U2A.5 | length 125.5
  Top Layer w10: R28A.1@-2820.96,1575 -2820.96,1530.71 cw(c-2834.74,1530.71) R12A.2@-2825,1520.96 -2820.08,1525.89 U2A.5@-2756.69,1525.89
NetR12B_1: R12B.1 R649B.2 U2B.8 | length 105.9
  Top Layer w10: R12B.1@-2825,1004.04 ccw(c-2813.12,1015.92) -2813.12,999.11 v1(-2790,999.11) U2B.8@-2756.69,999.11
  Bottom Layer w10: R649B.2@-2825,1004.04 ccw(c-2813.12,1015.92) -2813.12,999.11 v1(-2790,999.11)
NetR12B_2: R12B.2 R28B.1 U2B.5 | length 125.5
  Top Layer w10: R28B.1@-2820.96,1125 -2820.96,1080.71 cw(c-2834.74,1080.71) R12B.2@-2825,1070.96 -2820.08,1075.89 U2B.5@-2756.69,1075.89
NetR12C_1: R12C.1 R649C.2 U2C.8 | length 105.9
  Top Layer w10: R12C.1@-2825,554.04 ccw(c-2813.12,565.92) -2813.12,549.11 v1(-2790,549.11) U2C.8@-2756.69,549.11
  Bottom Layer w10: R649C.2@-2825,554.04 ccw(c-2813.12,565.92) -2813.12,549.11 v1(-2790,549.11)
NetR12C_2: R12C.2 R28C.1 U2C.5 | length 125.5
  Top Layer w10: R28C.1@-2820.96,675 -2820.96,630.71 cw(c-2834.74,630.71) R12C.2@-2825,620.96 -2820.08,625.89 U2C.5@-2756.69,625.89
NetR12D_1: R12D.1 R649D.2 U2D.8 | length 105.9
  Top Layer w10: R12D.1@-2825,104.04 ccw(c-2813.12,115.92) -2813.12,99.11 v1(-2790,99.11) U2D.8@-2756.69,99.11
  Bottom Layer w10: R649D.2@-2825,104.04 ccw(c-2813.12,115.92) -2813.12,99.11 v1(-2790,99.11)
NetR12D_2: R12D.2 R28D.1 U2D.5 | length 125.5
  Top Layer w10: R28D.1@-2820.96,225 -2820.96,180.71 cw(c-2834.74,180.71) R12D.2@-2825,170.96 -2820.08,175.89 U2D.5@-2756.69,175.89
NetR12E_1: R12E.1 R649E.2 U2E.8 | length 105.9
  Top Layer w10: R12E.1@-2825,-345.96 ccw(c-2813.12,-334.08) -2813.12,-350.89 v1(-2790,-350.89) U2E.8@-2756.69,-350.89
  Bottom Layer w10: R649E.2@-2825,-345.96 ccw(c-2813.12,-334.08) -2813.12,-350.89 v1(-2790,-350.89)
NetR12E_2: R12E.2 R28E.1 U2E.5 | length 125.5
  Top Layer w10: R28E.1@-2820.96,-225 -2820.96,-269.29 cw(c-2834.74,-269.29) R12E.2@-2825,-279.04 -2820.08,-274.11 U2E.5@-2756.69,-274.11
NetR12F_1: R12F.1 R649F.2 U2F.8 | length 105.9
  Top Layer w10: R12F.1@-2825,-795.96 ccw(c-2813.12,-784.08) -2813.12,-800.89 v1(-2790,-800.89) U2F.8@-2756.69,-800.89
  Bottom Layer w10: R649F.2@-2825,-795.96 ccw(c-2813.12,-784.08) -2813.12,-800.89 v1(-2790,-800.89)
NetR12F_2: R12F.2 R28F.1 U2F.5 | length 125.5
  Top Layer w10: R28F.1@-2820.96,-675 -2820.96,-719.29 cw(c-2834.74,-719.29) R12F.2@-2825,-729.04 -2820.08,-724.11 U2F.5@-2756.69,-724.11
NetR12G_1: R12G.1 R649G.2 U2G.8 | length 105.9
  Top Layer w10: R12G.1@-2825,-1245.96 ccw(c-2813.12,-1234.08) -2813.12,-1250.89 v1(-2790,-1250.89) U2G.8@-2756.69,-1250.89
  Bottom Layer w10: R649G.2@-2825,-1245.96 ccw(c-2813.12,-1234.08) -2813.12,-1250.89 v1(-2790,-1250.89)
NetR12G_2: R12G.2 R28G.1 U2G.5 | length 125.5
  Top Layer w10: R28G.1@-2820.96,-1125 -2820.96,-1169.29 cw(c-2834.74,-1169.29) R12G.2@-2825,-1179.04 -2820.08,-1174.11 U2G.5@-2756.69,-1174.11
NetR12H_1: R12H.1 R649H.2 U2H.8 | length 105.9
  Top Layer w10: R12H.1@-2825,-1695.96 ccw(c-2813.12,-1684.08) -2813.12,-1700.89 v1(-2790,-1700.89) U2H.8@-2756.69,-1700.89
  Bottom Layer w10: R649H.2@-2825,-1695.96 ccw(c-2813.12,-1684.08) -2813.12,-1700.89 v1(-2790,-1700.89)
NetR12H_2: R12H.2 R28H.1 U2H.5 | length 125.5
  Top Layer w10: R28H.1@-2820.96,-1575 -2820.96,-1619.29 cw(c-2834.74,-1619.29) R12H.2@-2825,-1629.04 -2820.08,-1624.11 U2H.5@-2756.69,-1624.11
NetR36A_1: R36A.1 R52A.2 U3A.4 | length 127.5
  Top Layer w10: U3A.4@-2593.31,1738.26 -2529.92,1738.26 cw(c-2529.92,1733.34) -2529.04,1738.18 R52A.2@-2529.04,1738.26 ; R36A.1@-2529.04,1787.37 R52A.2@-2529.04,1738.31 ; R52A.2@-2529.04,1738.31 cw(c-2529.92,1733.46) R52A.2@-2525,1733.46 cw(c-2525,1737.5) -2529.04,1737.5 R52A.2@-2529.04,1738.31
NetR36B_1: R36B.1 R52B.2 U3B.4 | length 127.5
  Top Layer w10: U3B.4@-2593.31,1288.26 -2529.92,1288.26 cw(c-2529.92,1283.34) -2529.04,1288.18 R52B.2@-2529.04,1288.26 ; R36B.1@-2529.04,1337.37 R52B.2@-2529.04,1288.31 ; R52B.2@-2529.04,1288.31 cw(c-2529.92,1283.46) R52B.2@-2525,1283.46 cw(c-2525,1287.5) -2529.04,1287.5 R52B.2@-2529.04,1288.31
NetR36C_1: R36C.1 R52C.2 U3C.4 | length 127.5
  Top Layer w10: U3C.4@-2593.31,838.26 -2529.92,838.26 cw(c-2529.92,833.34) -2529.04,838.18 R52C.2@-2529.04,838.26 ; R36C.1@-2529.04,887.37 R52C.2@-2529.04,838.31 ; R52C.2@-2529.04,838.31 cw(c-2529.92,833.46) R52C.2@-2525,833.46 cw(c-2525,837.5) -2529.04,837.5 R52C.2@-2529.04,838.31
NetR36D_1: R36D.1 R52D.2 U3D.4 | length 127.5
  Top Layer w10: U3D.4@-2593.31,388.26 -2529.92,388.26 cw(c-2529.92,383.34) -2529.04,388.18 R52D.2@-2529.04,388.26 ; R36D.1@-2529.04,437.37 R52D.2@-2529.04,388.31 ; R52D.2@-2529.04,388.31 cw(c-2529.92,383.46) R52D.2@-2525,383.46 cw(c-2525,387.5) -2529.04,387.5 R52D.2@-2529.04,388.31
NetR36E_1: R36E.1 R52E.2 U3E.4 | length 127.5
  Top Layer w10: U3E.4@-2593.31,-61.74 -2529.92,-61.74 cw(c-2529.92,-66.66) -2529.04,-61.82 R52E.2@-2529.04,-61.74 ; R36E.1@-2529.04,-12.63 R52E.2@-2529.04,-61.69 ; R52E.2@-2529.04,-61.69 cw(c-2529.92,-66.54) R52E.2@-2525,-66.54 cw(c-2525,-62.5) -2529.04,-62.5 R52E.2@-2529.04,-61.69
NetR36F_1: R36F.1 R52F.2 U3F.4 | length 127.5
  Top Layer w10: U3F.4@-2593.31,-511.74 -2529.92,-511.74 cw(c-2529.92,-516.66) -2529.04,-511.82 R52F.2@-2529.04,-511.74 ; R36F.1@-2529.04,-462.63 R52F.2@-2529.04,-511.69 ; R52F.2@-2529.04,-511.69 cw(c-2529.92,-516.54) R52F.2@-2525,-516.54 cw(c-2525,-512.5) -2529.04,-512.5 R52F.2@-2529.04,-511.69
NetR36G_1: R36G.1 R52G.2 U3G.4 | length 127.5
  Top Layer w10: U3G.4@-2593.31,-961.74 -2529.92,-961.74 cw(c-2529.92,-966.66) -2529.04,-961.82 R52G.2@-2529.04,-961.74 ; R36G.1@-2529.04,-912.63 R52G.2@-2529.04,-961.69 ; R52G.2@-2529.04,-961.69 cw(c-2529.92,-966.54) R52G.2@-2525,-966.54 cw(c-2525,-962.5) -2529.04,-962.5 R52G.2@-2529.04,-961.69
NetR36H_1: R36H.1 R52H.2 U3H.4 | length 127.5
  Top Layer w10: U3H.4@-2593.31,-1411.74 -2529.92,-1411.74 cw(c-2529.92,-1416.66) -2529.04,-1411.82 R52H.2@-2529.04,-1411.74 ; R36H.1@-2529.04,-1362.63 R52H.2@-2529.04,-1411.69 ; R52H.2@-2529.04,-1411.69 cw(c-2529.92,-1416.54) R52H.2@-2525,-1416.54 cw(c-2525,-1412.5) -2529.04,-1412.5 R52H.2@-2529.04,-1411.69
NetR44A_1: R44A.1 R60A.2 U2A.4 | length 118.6
  Top Layer w10: U2A.4@-2593.31,1525.89 -2530.92,1525.89 R60A.2@-2529.92,1526.89 ; R60A.2@-2529.04,1526 -2525,1521.97 R60A.2@-2525,1520.96 ; R60A.2@-2529.04,1526.89 R44A.1@-2529.04,1575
